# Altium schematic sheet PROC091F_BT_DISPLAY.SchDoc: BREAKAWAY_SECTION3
size 431 x 279 mm; Date: Not shown in title block; ApprovedBy: Not shown in title block; CheckedBy: Not shown in title block; Author: Not shown in title block; CompanyName: Not shown in title block; DrawnBy: Antony/Bala; Engineer: Not shown in title block; Organization: Not shown in title block; Address1: Not shown in title block; Address2: Not shown in title block; Address3: Not shown in title block; Address4: Not shown in title block; DocumentNumber: 9; Revision: Use project parameter SCH_Rev; SheetNumber: 9; SheetTotal: 12; PageSetup: Record=PageOptions¦CenterHorizontal=True¦CenterVertical=True¦PrintScale=1.00¦XCorrection=1.00¦YCorrection=1.00¦PrintKind=0¦BorderSize=5000000¦LeftOffset=0¦BottomOffset=0¦Orientation=2¦PaperLength=1000¦PaperWidth=1000¦Scale=100¦PaperSource=15¦PrintQuality=600¦MediaType=1¦DitherType=10¦PaperKind=Letter¦PrintScaleMode=1
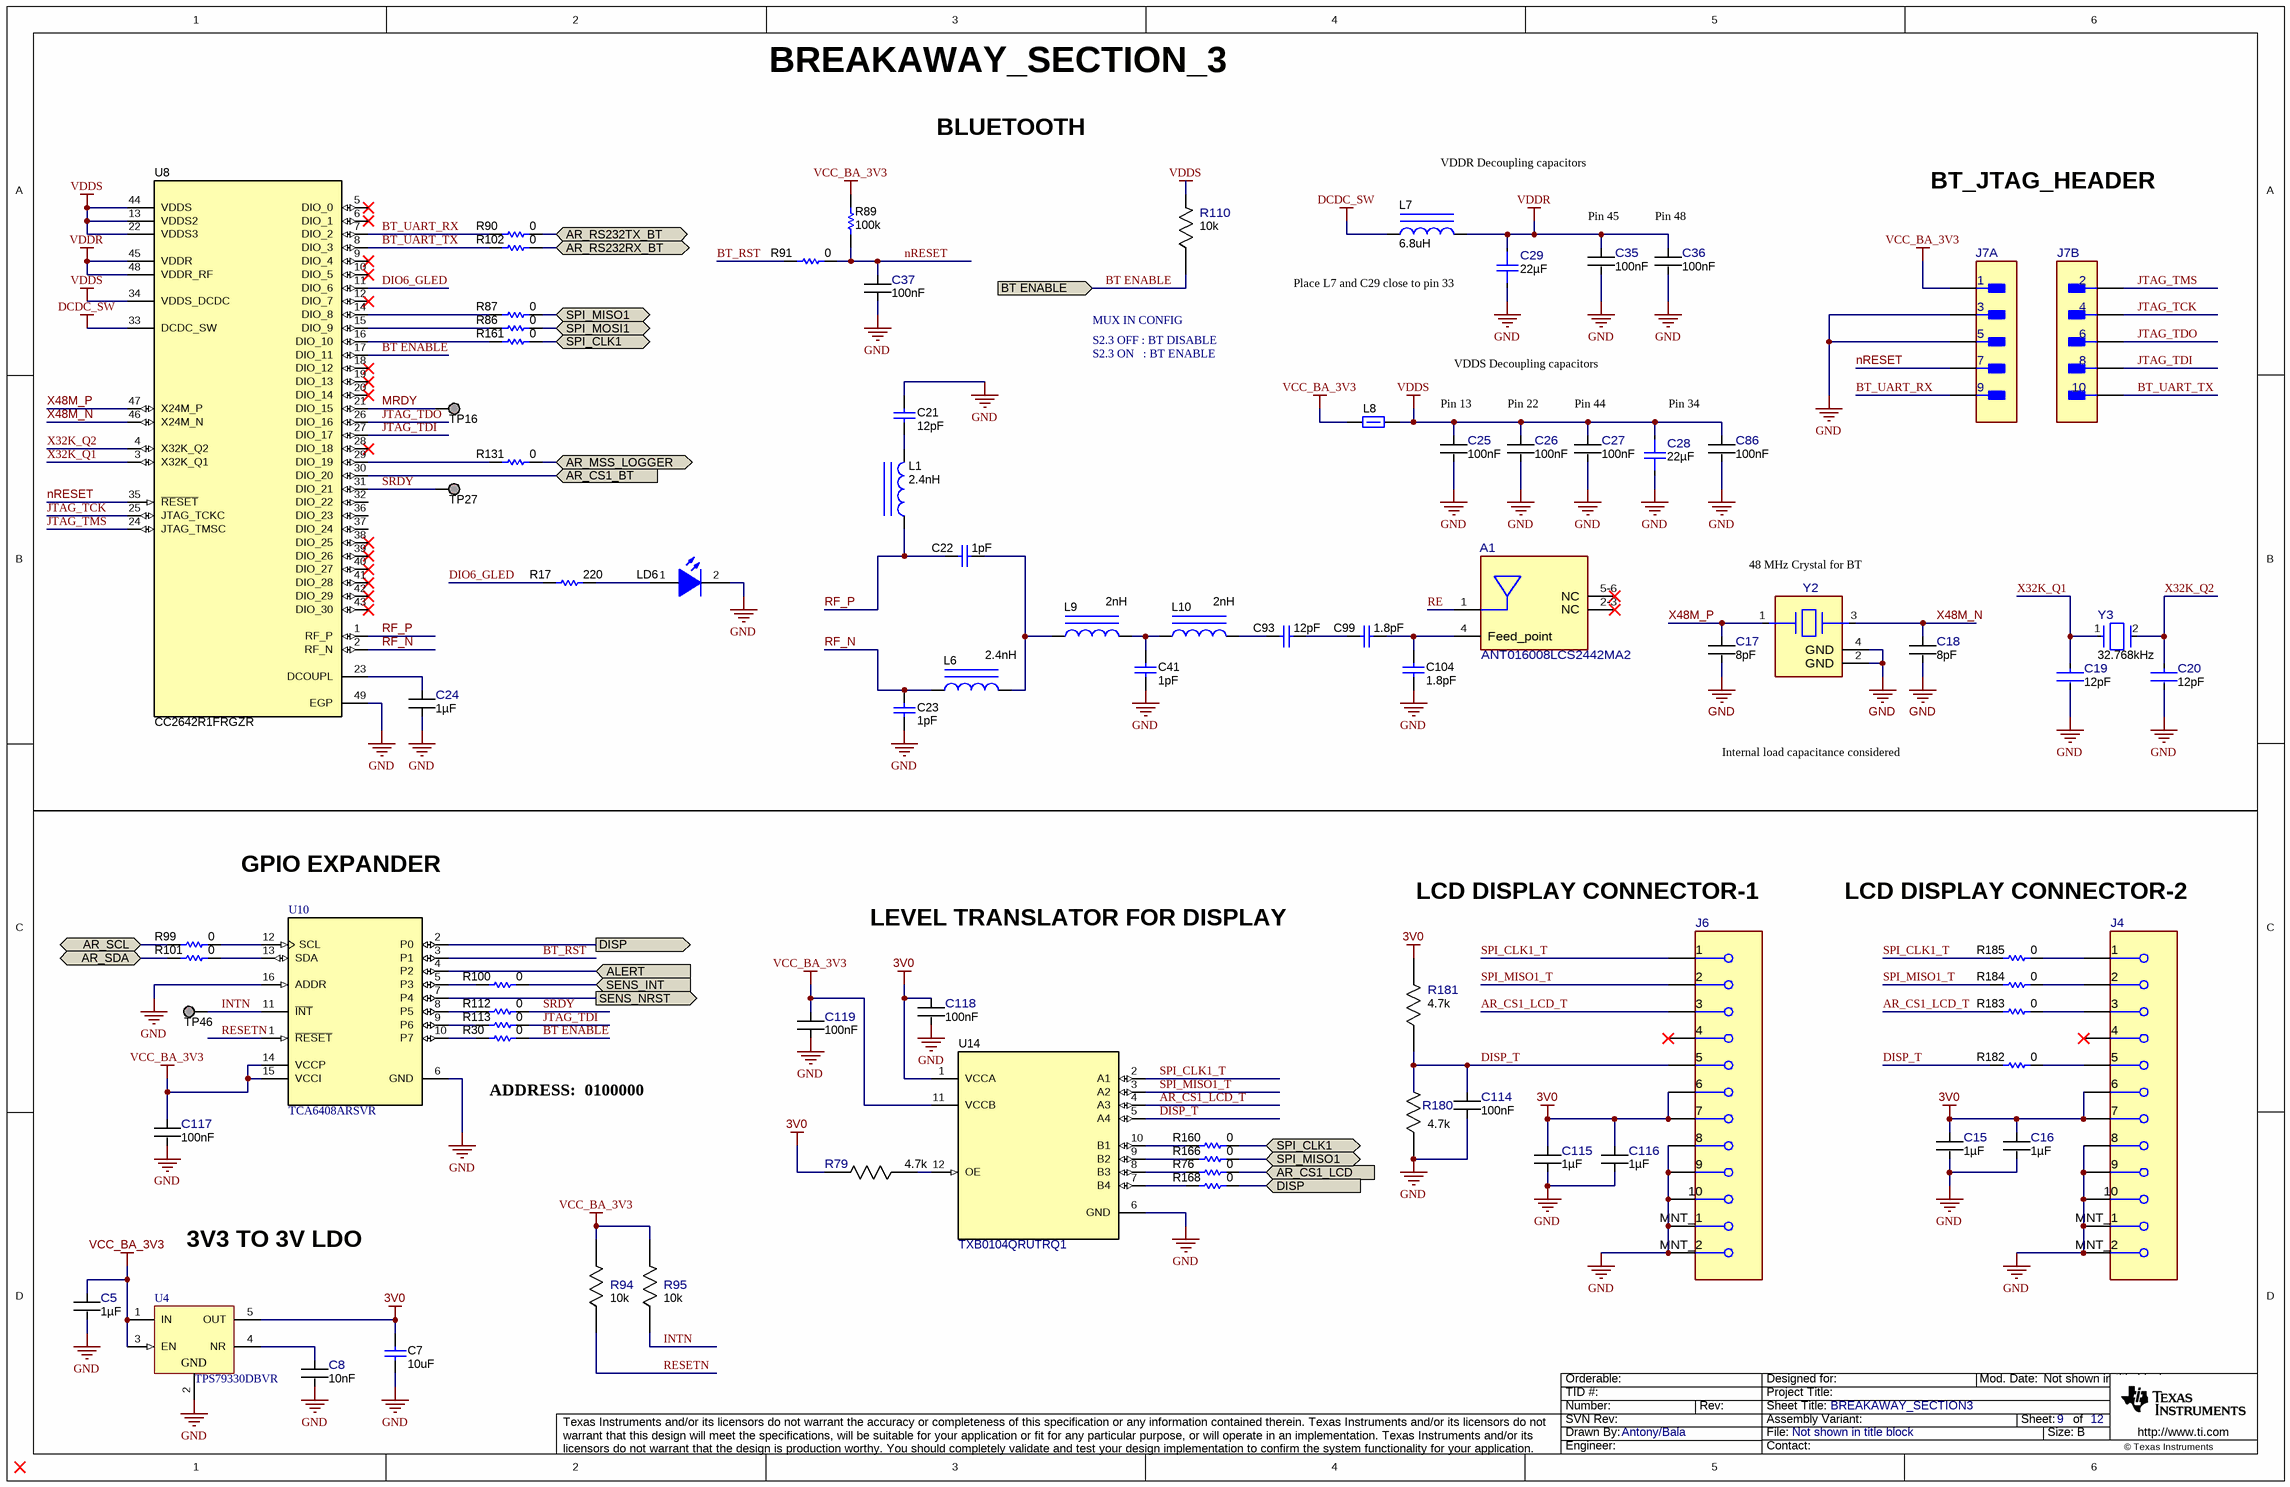
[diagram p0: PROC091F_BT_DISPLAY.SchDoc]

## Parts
A1  ANT016008LCS2442MA2  [FP-ANT016008LCS2442MA2_SMT_ANT-0]
C5  Cap_F: 1µF  [FP-CL03A105MO3NRNH_0201-IPC_C]  (hidden comment: CL03A105MO3NRNH)
C7  value 10uF  [0402_070]  (hidden comment: CL05A106MP5NUNC)
C8  Cap_F: 10nF  [FP-CL03A103KA3NNNC_0201-IPC_C]  (hidden comment: CL03A103KA3NNNC)
C15  Cap_F: 1µF  [FP-CL03A105MO3NRNH_0201-IPC_C]  (hidden comment: CL03A105MO3NRNH)
C16  Cap_F: 1µF  [FP-CL03A105MO3NRNH_0201-IPC_C]  (hidden comment: CL03A105MO3NRNH)
C17  Cap_F: 8pF  [FP-GRM0335C1H8R0BA01D_0201 (0603 metric)-IPC_C]  (hidden comment: GRM0335C1H8R0BA01D)
C18  Cap_F: 8pF  [FP-GRM0335C1H8R0BA01D_0201 (0603 metric)-IPC_C]  (hidden comment: GRM0335C1H8R0BA01D)
C19  Cap_F: 12pF  [FP-250R05L120JV4T_0201-IPC_C]  (hidden comment: 250R05L120JV4T)
C20  Cap_F: 12pF  [FP-250R05L120JV4T_0201-IPC_C]  (hidden comment: 250R05L120JV4T)
C21  ValueDisplayed: 12pF  [0402L]  (hidden comment: CL05C120JB5NNNC)
C22  ValueDisplayed: 1pF  [0402L]  (hidden comment: GCM1555C1H1R0CA16D)
C23  ValueDisplayed: 1pF  [0402L]  (hidden comment: GCM1555C1H1R0CA16D)
C24  Cap_F: 1µF  [FP-CL03A105MO3NRNH_0201-IPC_C]  (hidden comment: CL03A105MO3NRNH)
C25  Cap_F: 100nF  [FP-GRM033R6YA104KE14D_0201 (0603 Metric)-IPC_C]  (hidden comment: GRM033R6YA104KE14D)
C26  Cap_F: 100nF  [FP-GRM033R6YA104KE14D_0201 (0603 Metric)-IPC_C]  (hidden comment: GRM033R6YA104KE14D)
C27  Cap_F: 100nF  [FP-GRM033R6YA104KE14D_0201 (0603 Metric)-IPC_C]  (hidden comment: GRM033R6YA104KE14D)
C28  Cap_F: 22µF  [FP-CL05A226MQ5N6J8_0402-IPC_C]  (hidden comment: CL05A226MQ5N6J8)
C29  Cap_F: 22µF  [FP-CL05A226MQ5N6J8_0402-IPC_C]  (hidden comment: CL05A226MQ5N6J8)
C35  Cap_F: 100nF  [FP-GRM033R6YA104KE14D_0201 (0603 Metric)-IPC_C]  (hidden comment: GRM033R6YA104KE14D)
C36  Cap_F: 100nF  [FP-GRM033R6YA104KE14D_0201 (0603 Metric)-IPC_C]  (hidden comment: GRM033R6YA104KE14D)
C37  Cap_F: 100nF  [FP-GRM033R6YA104KE14D_0201 (0603 Metric)-IPC_C]  (hidden comment: GRM033R6YA104KE14D)
C41  ValueDisplayed: 1pF  [0402L]  (hidden comment: GCM1555C1H1R0CA16D)
C86  Cap_F: 100nF  [FP-GRM033R6YA104KE14D_0201 (0603 Metric)-IPC_C]  (hidden comment: GRM033R6YA104KE14D)
C93  ValueDisplayed: 12pF  [0402L]  (hidden comment: CL05C120JB5NNNC)
C99  ValueDisplayed: 1.8pF  [0402L]  (hidden comment: GJM1555C1H1R8BB01D)
C104  ValueDisplayed: 1.8pF  [0402L]  (hidden comment: GJM1555C1H1R8BB01D)
C114  Cap_F: 100nF  [FP-GRM033R6YA104KE14D_0201 (0603 Metric)-IPC_C]  (hidden comment: GRM033R6YA104KE14D)
C115  Cap_F: 1µF  [FP-CL03A105MO3NRNH_0201-IPC_C]  (hidden comment: CL03A105MO3NRNH)
C116  Cap_F: 1µF  [FP-CL03A105MO3NRNH_0201-IPC_C]  (hidden comment: CL03A105MO3NRNH)
C117  Cap_F: 100nF  [FP-GRM033R6YA104KE14D_0201 (0603 Metric)-IPC_C]  (hidden comment: GRM033R6YA104KE14D)
C118  Cap_F: 100nF  [FP-GRM033R6YA104KE14D_0201 (0603 Metric)-IPC_C]  (hidden comment: GRM033R6YA104KE14D)
C119  Cap_F: 100nF  [FP-GRM033R6YA104KE14D_0201 (0603 Metric)-IPC_C]  (hidden comment: GRM033R6YA104KE14D)
J4  51441-1093  [FP-51441-1093_CONN_SMD_FFC-0]  (value not drawn)
J6  51441-1093  [FP-51441-1093_CONN_SMD_FFC-0]  (value not drawn)
J7  GRPB052MWCN-RC  [FP-GRPB052MWCN-RC_HDR10-MFG]  (value not drawn)  (parts A,B of 2)
L1  ValueDisplayed: 2.4nH  [IND_LQG15H]  (hidden comment: LQG15HS2N4S02D)
L6  ValueDisplayed: 2.4nH  [IND_LQG15H]  (hidden comment: LQG15HS2N4S02D)
L7  ValueDisplayed: 6.8uH  [0805_HV]  (hidden comment: MLZ2012N6R8LT000)
L8  BLM18HE152SN1D  [0603L]  (value not drawn)
L9  ValueDisplayed: 2nH  [IND_LQG15H]  (hidden comment: LQG15HS2N0S02D)
L10  ValueDisplayed: 2nH  [IND_LQG15H]  (hidden comment: LQG15HS2N0S02D)
LD6  APHHS1005CGCK  [APHHS1005_Green]  (value not drawn)
R17  value 220  [0201L]  (hidden comment: RC0201JR-07220RL)
R30  Res_ohm: 0  [FP-RC0201JR-070RL_0201 (0603 Metric)-MFG]  (hidden comment: RC0201JR-070RL)
R76  Res_ohm: 0  [FP-RC0201JR-070RL_0201 (0603 Metric)-IPC_C]  (hidden comment: RC0201JR-070RL)
R79  Res_ohm: 4.7k  [FP-ERJ-1GNF4701C_0201-IPC_C]  (hidden comment: ERJ-1GNF4701C)
R86  Res_ohm: 0  [FP-RC0201JR-070RL_0201 (0603 Metric)-IPC_C]  (hidden comment: RC0201JR-070RL)
R87  Res_ohm: 0  [FP-RC0201JR-070RL_0201 (0603 Metric)-IPC_C]  (hidden comment: RC0201JR-070RL)
R89  value 100k  [0201L]  (hidden comment: CRCW0201100KFKED)
R90  Res_ohm: 0  [FP-RC0201JR-070RL_0201 (0603 Metric)-IPC_C]  (hidden comment: RC0201JR-070RL)
R91  Res_ohm: 0  [FP-RC0201JR-070RL_0201 (0603 Metric)-IPC_C]  (hidden comment: RC0201JR-070RL)
R94  Res_ohm: 10k  [FP-RR0306P-103-D_0201-IPC_C]  (hidden comment: RR0306P-103-D)
R95  Res_ohm: 10k  [FP-RR0306P-103-D_0201-IPC_C]  (hidden comment: RR0306P-103-D)
R99  Res_ohm: 0  [FP-RC0201JR-070RL_0201 (0603 Metric)-IPC_C]  (hidden comment: RC0201JR-070RL)
R100  Res_ohm: 0  [FP-RC0201JR-070RL_0201 (0603 Metric)-IPC_C]  (hidden comment: RC0201JR-070RL)
R101  Res_ohm: 0  [FP-RC0201JR-070RL_0201 (0603 Metric)-IPC_C]  (hidden comment: RC0201JR-070RL)
R102  Res_ohm: 0  [FP-RC0201JR-070RL_0201 (0603 Metric)-IPC_C]  (hidden comment: RC0201JR-070RL)
R110  Res_ohm: 10k  [FP-RR0306P-103-D_0201-IPC_C]  (hidden comment: RR0306P-103-D)
R112  Res_ohm: 0  [FP-RC0201JR-070RL_0201 (0603 Metric)-IPC_C]  (hidden comment: RC0201JR-070RL)
R113  Res_ohm: 0  [FP-RC0201JR-070RL_0201 (0603 Metric)-IPC_C]  (hidden comment: RC0201JR-070RL)
R131  Res_ohm: 0  [FP-RC0201JR-070RL_0201 (0603 Metric)-IPC_C]  (hidden comment: RC0201JR-070RL)
R160  Res_ohm: 0  [FP-RC0201JR-070RL_0201 (0603 Metric)-IPC_C]  (hidden comment: RC0201JR-070RL)
R161  Res_ohm: 0  [FP-RC0201JR-070RL_0201 (0603 Metric)-IPC_C]  (hidden comment: RC0201JR-070RL)
R166  Res_ohm: 0  [FP-RC0201JR-070RL_0201 (0603 Metric)-IPC_C]  (hidden comment: RC0201JR-070RL)
R168  Res_ohm: 0  [FP-RC0201JR-070RL_0201 (0603 Metric)-IPC_C]  (hidden comment: RC0201JR-070RL)
R180  Res_ohm: 4.7k  [FP-ERJ-1GNF4701C_0201-IPC_C]  (hidden comment: ERJ-1GNF4701C)
R181  Res_ohm: 4.7k  [FP-ERJ-1GNF4701C_0201-IPC_C]  (hidden comment: ERJ-1GNF4701C)
R182  Res_ohm: 0  [FP-RC0201JR-070RL_0201 (0603 Metric)-IPC_C]  (hidden comment: RC0201JR-070RL)
R183  Res_ohm: 0  [FP-RC0201JR-070RL_0201 (0603 Metric)-IPC_C]  (hidden comment: RC0201JR-070RL)
R184  Res_ohm: 0  [FP-RC0201JR-070RL_0201 (0603 Metric)-IPC_C]  (hidden comment: RC0201JR-070RL)
R185  Res_ohm: 0  [FP-RC0201JR-070RL_0201 (0603 Metric)-IPC_C]  (hidden comment: RC0201JR-070RL)
TP16  TESTPOINT  [TP_25MIL-SMT]  (value not drawn)  (no BOM)
TP27  TESTPOINT  [TP_25MIL-SMT]  (value not drawn)  (no BOM)
TP46  TESTPOINT  [TP_25MIL-SMT]  (value not drawn)  (no BOM)
U4  TPS79330DBVR  [DBV0005A_N]
U8  CC2642R1FRGZR  [RGZ0048A]
U10  TCA6408ARSVR  [RSV0016A]
U14  TXB0104QRUTRQ1  [RUT0012A]
Y2  CX2016DB48000C0WPLA2  [FP-CX2016DB48000C0WPLA2_SMD4-MFG]  (value not drawn)
Y3  Frequency_Fixed: 32.768kHz  [FP-ABS05W-32.768KHZ-D-2-T_XTAL_SMT_1MM6_1MM0-MFG]  (hidden comment: ABS05W-32.768KHZ-D-2-T)

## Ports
ALERT (in), AR_CS1_BT (in), AR_CS1_LCD (in), AR_MSS_LOGGER (bidir), AR_RS232RX_BT (bidir), AR_RS232TX_BT (bidir), AR_SCL (bidir), AR_SDA (bidir), BT ENABLE (in), DISP (in), DISP (out), SENS_INT (in), SENS_NRST (out), SPI_CLK1 (bidir), SPI_MISO1 (bidir), SPI_MOSI1 (bidir)

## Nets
3V0: C7.1 C15.1 C16.1 C115.1 C116.1 C118.1 J4.6 J4.7 J6.6 J6.7 R79.2 R181.2 U4.5(OUT) U14.1(VCCA)
DCDC_SW: L7.1 U8.33(DCDC_SW)
GND: C5.2 C7.2 C8.2 C15.2 C16.2 C17.2 C18.2 C19.2 C20.2 C21.1 C23.2 C24.2 C25.2 C26.2 C27.2 C28.2 C29.2 C35.2 C36.2 C37.2 C41.2 C86.2 C104.2 C114.1 C115.2 C116.2 C117.2 C118.2 C119.2 J4.8 J4.9 J4.10 J4.11(MNT_1) J4.12(MNT_2) J6.8 J6.9 J6.10 J6.11(MNT_1) J6.12(MNT_2) J7.3 J7.5 LD6.2(K) R180.1 U4.2(GND) U8.49(EGP) U10.6(GND) U10.16(ADDR) U14.6(GND) Y2.2(GND) Y2.4(GND)
VCC_BA_3V3: C5.1 C117.1 C119.1 J7.1 L8.1 R89.2 R94.2 R95.2 U4.1(IN) U4.3(EN) U10.14(VCCP) U10.15(VCCI) U14.11(VCCB)
VDDR: C29.1 C35.1 C36.1 L7.2 U8.45(VDDR) U8.48(VDDR_RF)
VDDS: C25.1 C26.1 C27.1 C28.1 C86.1 L8.2 R110.2 U8.13(VDDS2) U8.22(VDDS3) U8.34(VDDS_DCDC) U8.44(VDDS)
ALERT: U10.4(P2) ; port ALERT
AR_CS1_BT: U8.30(DIO_20) ; port AR_CS1_BT
AR_CS1_LCD: R76.2 ; port AR_CS1_LCD
AR_CS1_LCD_T: J6.3 R183.1 U14.4(A3)
AR_MSS_LOGGER: R131.1 ; port AR_MSS_LOGGER
AR_RS232RX_BT: R102.1 ; port AR_RS232RX_BT
AR_RS232TX_BT: R90.1 ; port AR_RS232TX_BT
AR_SCL: R99.2 ; port AR_SCL
AR_SDA: R101.2 ; port AR_SDA
BT ENABLE: R30.1 R110.1 U8.17(DIO_11) ; port BT ENABLE
BT_RST: R91.2 U10.3(P1)
BT_UART_RX: J7.9 R90.2 U8.7(DIO_2)
BT_UART_TX: J7.10 R102.2 U8.8(DIO_3)
DIO6_GLED: R17.1 U8.11(DIO_6)
DISP: R168.2 U10.2(P0) ; port DISP
DISP_T: C114.2 J6.5 R180.2 R181.1 R182.1 U14.5(A4)
INTN: R95.1 TP46.1 U10.11(~{INT})
JTAG_TCK: J7.4 U8.25(JTAG_TCKC)
JTAG_TDI: J7.8 R113.1 U8.27(DIO_17)
JTAG_TDO: J7.6 U8.26(DIO_16)
JTAG_TMS: J7.2 U8.24(JTAG_TMSC)
MRDY: TP16.1 U8.21(DIO_15)
nRESET: C37.1 J7.7 R89.1 R91.1 U8.35(~{RESET})
RE: A1.1(Radiator_electrode)
RESETN: R94.1 U10.1(~{RESET})
RF_N: C23.1 L6.1 U8.2(RF_N)
RF_P: C22.2 L1.1 U8.1(RF_P)
SENS_INT: R100.1 ; port SENS_INT
SENS_NRST: U10.7(P4) ; port SENS_NRST
SPI_CLK1: R160.2 R161.1 ; port SPI_CLK1
SPI_CLK1_T: J6.1 R185.1 U14.2(A1)
SPI_MISO1: R87.1 R166.2 ; port SPI_MISO1
SPI_MISO1_T: J6.2 R184.1 U14.3(A2)
SPI_MOSI1: R86.1 ; port SPI_MOSI1
SRDY: R112.1 TP27.1 U8.31(DIO_21)
X32K_Q1: C19.1 U8.3(X32K_Q1) Y3.1
X32K_Q2: C20.1 U8.4(X32K_Q2) Y3.2
X48M_N: C18.1 U8.46(X24M_N) Y2.3(2_HOT)
X48M_P: C17.1 U8.47(X24M_P) Y2.1(1_HOT)
NetA1_4: A1.4(Feed_point) C99.1 C104.1
NetC8_1: C8.1 U4.4(NR)
NetC21_2: C21.2 L1.2
NetC22_1: C22.1 L6.2 L9.1
NetC24_1: C24.1 U8.23(DCOUPL)
NetC41_1: C41.1 L9.2 L10.1
NetC93_1: C93.1 C99.2
NetC93_2: C93.2 L10.2
NetJ4_1: J4.1 R185.2
NetJ4_2: J4.2 R184.2
NetJ4_3: J4.3 R183.2
NetJ4_5: J4.5 R182.2
NetLD6_1: LD6.1(A) R17.2
NetR30_2: R30.2 U10.10(P7)
NetR76_1: R76.1 U14.8(B3)
NetR79_1: R79.1 U14.12(OE)
NetR86_2: R86.2 U8.15(DIO_9)
NetR87_2: R87.2 U8.14(DIO_8)
NetR99_1: R99.1 U10.12(SCL)
NetR100_2: R100.2 U10.5(P3)
NetR101_1: R101.1 U10.13(SDA)
NetR112_2: R112.2 U10.8(P5)
NetR113_2: R113.2 U10.9(P6)
NetR131_2: R131.2 U8.29(DIO_19)
NetR160_1: R160.1 U14.10(B1)
NetR161_2: R161.2 U8.16(DIO_10)
NetR166_1: R166.1 U14.9(B2)
NetR168_1: R168.1 U14.7(B4)

Not connected (* = marked no-connect by the designer): A1 2-3(NC)* 5-6(NC)*; J4 4*; J6 4*; U8 5(DIO_0)* 6(DIO_1)* 9(DIO_4)* 10(DIO_5)* 12(DIO_7)* 18(DIO_12)* 19(DIO_13)* 20(DIO_14)* 28(DIO_18)* 32(DIO_22) 36(DIO_23) 37(DIO_24) 38(DIO_25)* 39(DIO_26)* 40(DIO_27)* 41(DIO_28)* 42(DIO_29)* 43(DIO_30)*

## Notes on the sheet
- BREAKAWAY_SECTION_3
- BLUETOOTH
- VDDR Decoupling capacitors
- Pin 45
- (near C36) Pin 48
- BT_JTAG_HEADER
- Place L7 and C29 close to pin 33
- MUX IN CONFIG
- S2.3 ON   : BT ENABLE
- S2.3 OFF : BT DISABLE
- VDDS Decoupling capacitors
- Pin 13
- Pin 22
- Pin 44
- Pin 34
- 48 MHz Crystal for BT
- Internal load capacitance considered
- GPIO EXPANDER
- LCD DISPLAY CONNECTOR-1
- LCD DISPLAY CONNECTOR-2
- LEVEL TRANSLATOR FOR DISPLAY
- ADDRESS:  0100000
- 3V3 TO 3V LDO

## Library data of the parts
A1 = CMP-0087189-1: RF ANT 2.4GHZ CHIP SOLDER SMD; Manufacturer: TDK Corporation; SizeZ_mm: 0.4mm
C5 C15 C16 C24 C115 C116 = CMP-0086446-1: 1µF ±20% 16V Ceramic Capacitor X5R 0201; Manufacturer: Samsung Electro-Mechanics; AEC Qualified: No; SizeZ_mm: 0.39mm; Symbol Name: SYM-CL03A105MO3NRNH; TempCo: 15%
C7 = CMP-0006339-4: CAP, CERM, 10 uF, 10 V, +/- 20%, X5R, 0402; Manufacturer: Samsung Electro-Mechanics; AEC Category: Q200; AEC Qualified: N; Cap_Case: 0402; Cap_F: 10µF; SizeArea_mm2: 0.5; SizeAreaWB_mm2: 3; SizeX_mm: 1; SizeZ_mm: 0.6; TaMax_C: 85°C; TaMin_C: -55°C; U/M: EA; Value1: Unknown; Value2: 10V
C8 = CMP-0086445-1: CAP CER 10000PF 25V X5R 0201; Manufacturer: Samsung Electro-Mechanics America, Inc; AEC Qualified: No; SizeZ_mm: 0.33mm; Symbol Name: SYM-CL03A103KA3NNNC; TempCo: 15%; Tolerance_%: 10%
C17 C18 = CMP-0086441-1: Cap Ceramic 8pF 50V C0G 0.1pF SMD 0201 125°C Paper T/R; Manufacturer: Murata; AEC Qualified: No; SizeZ_mm: 0.33mm; Symbol Name: SYM-GRM0335C1H8R0BA01D; TempCo: 30ppm/°C
C19 C20 = CMP-0087190-1: CAP CER 12PF 25V C0G/NP0 0201; Manufacturer: Johanson Technology Inc.; AEC Grade: Grade 1; AEC Qualified: Yes; SizeZ_mm: 0.33mm; Symbol Name: SYM-250R05L120JV4T; TempCo: 30ppm/°C; Tolerance_%: 5%
C21 C93 = CMP-0006345-2: CAP, CERM, 12 pF, 50 V, +/- 5%, C0G/NP0, 0402; Manufacturer: Samsung Electro-Mechanics; TaMin_C: -55°C; Polarized: N; SizeAreaWB_mm2: 3; Value1: Unknown; U/M: EA; Value: 12pF; TaMax_C: 125°C; SizeZ_mm: 0.6; SizeX_mm: 1; SizeY_mm: 0.5; Cap_Case: 0402; Value2: 50V; AEC Category: Q200
C22 C23 C41 = CMP-0085178-1: CAP, CERM, 1 pF, 50 V,+/- 25%, C0G/NP0, AEC-Q200 Grade 1, 0402; Manufacturer: MuRata; SizeX_mm: 1; Polarized: N; AEC Qualified: Y; AEC Category: Q200; VDC_V: 50V; Cap_Case: 0402; TaMax_C: 125°C; TaMin_C: -55°C; U/M: EA; Value: 1pF; SizeY_mm: 0.5; SizeAreaWB_mm2: 3; SizeZ_mm: 0.6
C25-C27 C35-C37 C86 C114 C117-C119 = CMP-0086440-1: Cap Ceramic 0.1uF 35V X5R 10% Pad SMD 0201 85C T/R; Manufacturer: Murata Electronics North America; AEC Qualified: No; SizeZ_mm: 0.33mm; Symbol Name: SYM-GRM033R6YA104KE14D; TempCo: 15%
C28 C29 = CMP-0089043-3: CAP CER 22UF 6.3V X5R 0402; Manufacturer: Samsung Electro-Mechanics; AEC Qualified: No; SizeZ_mm: 0.55mm; TempCo: 15%; Tolerance_%: 20%
C99 C104 = CMP-0086306-1: CAP, CERM, 1.8 pF, 50 V,+/- 6%, C0G/NP0, 0402; Manufacturer: MuRata; VDC_V: 50V; SizeZ_mm: 0.6; SizeAreaWB_mm2: 3; SizeArea_mm2: 0.5; Polarized: N; TaMax_C: 125°C; Cap_Case: 0402; SizeX_mm: 1; Value: 1.8pF; U/M: EA; TaMin_C: -55°C; AEC Category: Q200
J4 J6 = CMP-0086453-1: Easy-On™ Type FFC/FPC Connector, Right-Angle, Surface Mount, ZIF, Bottom Contact Style, 1.10mm Mated Height, 10 Circuits; Manufacturer: Molex
J7 = CMP-0087786-1: CONN HEADER R/A 10POS 1.27MM; Manufacturer: Sullins; Row_Count: 2; Current_A: 1A; ContactFinish: Gold
L1 L6 = CMP-0058626-1: Inductor, Multilayer, Air Core, 2.4 nH, 0.3 A, 0.15 ohm, SMD; Manufacturer: MuRata; Isat: 0.3A @ % inductance drop; Irms: 0.3A @ C rise; Green_Lifecycle: Active; SizeAreaWB_mm2: 3; DCR_ohm: 0.15; Green_REACh: Passed; Value: 2.4nH; Imax_A: 300mA; SizeZ_mm: 0.55; SizeX_mm: 1; SizeY_mm: 0.5; Value2: 0.3A; AEC Category: Q200
L7 = CMP-0062727-1: Inductor, Multilayer, Ferrite, 6.8 uH, 0.11 A, 0.25 ohm, SMD; Manufacturer: TDK; Isat: 0.11A @ 50% inductance drop; Irms: 0.55A @ 20C rise; Green_Lifecycle: Active; SizeAreaWB_mm2: 6.75; DCR_ohm: 0.25; Green_REACh: Passed; Value: 6.8uH; Imax_A: 110mA; SizeZ_mm: 1.45; SizeX_mm: 2; SizeY_mm: 1.25; Value2: 0.11A; SizeArea_mm2: 2.5; Ind_H: 6.8µH; AEC Category: Q200
L8 = CMP-0003349-2: Ferrite Bead, 1500 ohm @ 100 MHz, 0.5 A, 0603; Manufacturer: MuRata; Ztyp@1GHz_Ohm: 1.5k; SizeAreaWB_mm2: 4.68; DCR_ohm: 0.5; Value1: 0.5 ohm; Imax_A: 500mA; SizeZ_mm: 1; SizeX_mm: 1.6; SizeY_mm: 0.8; Value2: 0.5A; SizeArea_mm2: 1.28
L9 L10 = CMP-0058624-1: Inductor, Multilayer, Air Core, 2 nH, 0.3 A, 0.1 ohm, SMD; Manufacturer: MuRata; Isat: 0.3A @ % inductance drop; Irms: 0.3A @ C rise; Green_Lifecycle: Active; SizeAreaWB_mm2: 3; DCR_ohm: 0.1; Green_REACh: Passed; Value1: 0.1 ohm; Value: 2nH; Imax_A: 300mA; SizeZ_mm: 0.55; SizeX_mm: 1; SizeY_mm: 0.5; Value2: 0.3A; AEC Category: Q200
LD6 = CMP-0067682-2: LED, Green, SMD; Manufacturer: Kingbright; Angle: 120.0; Power_TotalModule: 75mW; SizeZ_mm: 0.6; Vf_V: 2.1V; Vr_V: 5V; Io_A: 20mA; Ir_A: 10µA; SizeArea_mm2: 0.5; SizeAreaWB_mm2: 3.0; SizeX_mm: 1.0; Tjmax_C: 85°C; Value1: 0.075W
R17 = CMP-0027072-1: RES, 220, 5%, 0.05 W, 0201; Manufacturer: Yageo America; AEC Category: Q200; AEC Qualified: N; EIA_Code: E24; Power_W: 50mW; SizeArea_mm2: 0.18; SizeX_mm: 0.6; SizeY_mm: 0.3; SizeZ_mm: 0.26; TempCo: 200 ppm/C; U/M: EA; Value2: 0.05W; Value_Code: 220R; VDC_V: 25V
R30 R76 R86 R87 R90 R91 R99-R102 R112 R113 R131 R160 R161 R166 R168 R182-R185 = CMP-0086442-2: RES SMD 0 OHM JUMPER 1/20W 0201; Manufacturer: Yageo; AEC Qualified: No; Power_W: 50mW; SizeZ_mm: 0.26mm; TempCo: 200ppm/°C; Tolerance_%: 5%; VDC_V: 25V
R79 R180 R181 = CMP-0087184-1: RESISTOR, 0201, 0.05W, 1%, 4K7; Manufacturer: Panasonic Electronic Components; AEC Grade: Grade 1; AEC Qualified: Yes; Power_W: 50mW; SizeZ_mm: 0.26mm; Symbol Name: SYM-ERJ-1GNF4701C; TempCo: 200ppm/°C; VDC_V: 25V
R89 = CMP-0027261-3: RES, 100 k, 1%, 0.05 W, 0201; Manufacturer: Vishay-Dale; AEC Category: Q200; AEC Qualified: N; EIA_Code: E96; Power_W: 50mW; SizeArea_mm2: 0.18; SizeX_mm: 0.6; SizeY_mm: 0.3; SizeZ_mm: 0.26; TempCo: 100 ppm/C; Value2: 0.05W; VDC_V: 30V
R94 R95 R110 = CMP-0088002-1: 10 kOhms ±0.5% 0.05W, 1/20W Chip Resistor 0201 (0603 Metric)  Thin Film; Manufacturer: Susumu; AEC Qualified: No; Power_W: 50mW; SizeZ_mm: 0.26mm; Symbol Name: SYM-RR0306P-103-D; TempCo: 25ppm/°C; VDC_V: 15V
TP16 TP27 TP46 = CMP-0078143-3: TEST POINT.  No entry in BOM.
U4 = CMP-0035419-1: Single Output High PSRR LDO, 200 mA, Fixed 3 V Output, 2.7 to 5.5 V Input, 5-pin SOT-23 (DBV), -40 to 85 degC, Green (RoHS & no Sb/Br); Manufacturer: Texas Instruments; Accuracy(%): 2; Fixed Output Options(V): 3; Iout(Max)(A): 0.2; Rating: Catalog; SubFamily: Single Channel LDO; Vdo(Typ)(mV): 112; Vin(Max)(V): 5.5; Vin(Min)(V): 2.7
U8 = CMP-0083675-2: SimpleLink(TM) Bluetooth(R) 5 low energy Wireless MCU, RGZ0048A (VQFN-48); Alternate Manufacturer: Texas Instruments; Alternate PartNumber: CC2642R1FRGZT; SizeZ_mm: 1; AEC Category: Q200; SizeY_mm: 7; Rating: #N/A; SizeAreaWB_mm2: 81; AEC Qualified: N; CompType: IC; SizeArea_mm2: 49
U10 = CMP-0043349-1: Low-Voltage 8-Bit I2C and SMBus I/O Expander, 1.65 to 5.5 V, -40 to 85 degC, 16-pin UQFN (RSV), Green (RoHS & no Sb/Br); Manufacturer: Texas Instruments; # of I/Os: 8; 5V Tolerant I/O: Yes; fSCLK(Max)(MHz): 400; I2C Address: 0100 00x; SubFamily: I2C IO Expander; VCC(Max)(V): 5.5; VCC(Min)(V): 1.65
U14 = CMP-0860038-1: Automotive 4-Bit Bidirectional Voltage-Level Translator with Auto Direction Sensing and +/-15kV ESD, RUT0012A (UQFN-12); Alternate Manufacturer: Texas Instruments; AEC Category: Q200; AEC Qualified: Y; CompType: IC; SizeArea_mm2: 3.4; SizeAreaWB_mm2: 8.1; SizeX_mm: 1.7; SizeY_mm: 2; SizeZ_mm: 0.55
Y2 = CMP-0088076-1: 48MHz ±20ppm Crystal 7pF 50 Ohms 4-SMD, No Lead; Manufacturer: Kyocera; SizeZ_mm: 0.45mm
Y3 = CMP-0088006-1: CRYSTAL 32.768KHZ 4PF SMD; Manufacturer: Abracon LLC; AEC Qualified: No; Frequency Tolerance: 20ppm; SizeZ_mm: 0.5mm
